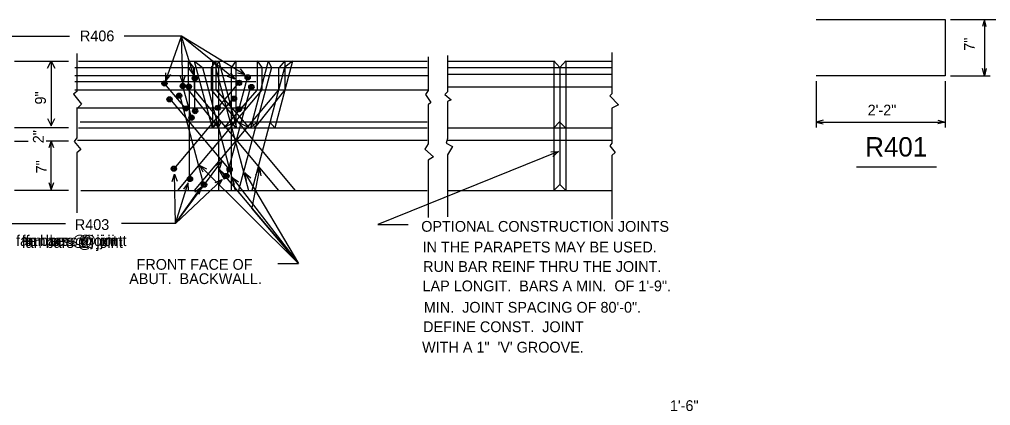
# Model space of a CAD drawing. Extents: x -3.6 to 32.6, y 15.5 to 40.2.
# Drawn here: x 9.24 to 20.52, y 24.58 to 29.06 of the extents above; entities that cross this region are included whole.
import ezdxf

# ---------------------------------------------------------------- set-up
doc = ezdxf.new("R2010")
doc.units = 0
for name, color, linetype in [('Level 2', 7, 'Continuous'), ('Level 3', 7, 'Continuous'), ('Level 4', 7, 'Continuous'), ('Level 5', 7, 'Continuous'), ('Level 6', 7, 'Continuous'), ('Level 7', 7, 'Continuous')]:
    doc.layers.add(name, color=color, linetype=linetype)

msp = doc.modelspace()

# ---------------------------------------------------------------- linework, layer by layer
at = {"layer": 'Level 2'}
for p, q in [((18.495, 29.063), (19.995, 29.063)), ((19.995, 29.063), (19.995, 28.411)), ((20.058, 29.063), (20.583, 29.063)), ((20.451, 29.055), (20.451, 28.432)), ((9.087, 28.87), (9.822, 28.87)), ((11.121, 28.87), (10.457, 28.87)), ((9.907, 28.668), (9.907, 28.229)), ((16.121, 28.678), (16.121, 28.199)), ((9.181, 28.58), (9.809, 28.58)), ((9.61, 28.58), (9.61, 27.834)), ((9.61, 28.58), (9.61, 27.83)), ((13.988, 28.631), (13.988, 28.238)), ((14.215, 28.647), (14.215, 28.223)), ((14.215, 28.58), (15.447, 28.58)), ((15.447, 28.584), (15.447, 27.08)), ((15.517, 28.505), (15.447, 28.584)), ((15.588, 28.584), (15.517, 28.505)), ((15.588, 28.584), (15.588, 27.08)), ((15.595, 28.58), (16.121, 28.58)), ((14.215, 28.505), (16.121, 28.505)), ((15.517, 28.505), (15.517, 27.15)), ((14.215, 28.43), (16.128, 28.43)), ((19.995, 28.411), (18.495, 28.411)), ((18.495, 28.348), (18.495, 27.811)), ((19.995, 28.348), (19.995, 27.811)), ((20.058, 28.411), (20.519, 28.411)), ((9.907, 28.229), (9.868, 28.198)), ((13.988, 28.238), (13.956, 28.192)), ((14.215, 28.223), (14.183, 28.192)), ((14.215, 28.28), (16.128, 28.28)), ((9.868, 28.198), (9.962, 28.08)), ((13.956, 28.192), (14.019, 28.098)), ((14.019, 28.098), (13.988, 28.074)), ((14.183, 28.192), (14.254, 28.129)), ((14.254, 28.129), (14.215, 28.113)), ((14.215, 28.113), (14.215, 27.682)), ((16.121, 28.199), (16.098, 28.176)), ((16.098, 28.176), (16.199, 28.074)), ((9.962, 28.08), (9.907, 28.025)), ((9.907, 28.025), (9.907, 27.688)), ((13.988, 28.074), (13.988, 27.619)), ((16.199, 28.074), (16.121, 28.035)), ((16.121, 28.035), (16.121, 27.627)), ((15.517, 27.878), (15.447, 27.807)), ((15.513, 27.876), (15.584, 27.805)), ((18.495, 27.873), (19.996, 27.873)), ((9.184, 27.81), (9.812, 27.81)), ((14.215, 27.805), (16.121, 27.805)), ((9.181, 27.651), (9.34, 27.651)), ((9.809, 27.651), (9.552, 27.651)), ((9.61, 27.088), (9.61, 27.656)), ((9.907, 27.688), (9.875, 27.648)), ((9.875, 27.648), (9.954, 27.554)), ((14.215, 27.682), (14.199, 27.627)), ((14.21, 27.663), (16.121, 27.663)), ((9.954, 27.554), (9.907, 27.515)), ((15.504, 27.531), (13.403, 26.685)), ((13.988, 27.619), (13.948, 27.557)), ((13.948, 27.557), (14.05, 27.47)), ((14.199, 27.627), (14.27, 27.588)), ((14.27, 27.588), (14.215, 27.493)), ((16.121, 27.627), (16.098, 27.596)), ((16.098, 27.596), (16.16, 27.518)), ((9.907, 27.515), (9.907, 26.819)), ((14.05, 27.47), (13.988, 27.431)), ((13.988, 27.431), (13.988, 26.764)), ((14.215, 27.493), (14.215, 26.772)), ((16.16, 27.518), (16.121, 27.486)), ((16.121, 27.486), (16.121, 26.748)), ((18.964, 27.354), (19.893, 27.354)), ((9.181, 27.084), (9.809, 27.084)), ((14.215, 27.08), (16.121, 27.08)), ((15.517, 27.15), (15.447, 27.079)), ((15.517, 27.15), (15.588, 27.079)), ((9.025, 26.696), (9.777, 26.696)), ((11.052, 26.696), (10.425, 26.696)), ((13.403, 26.685), (13.755, 26.685)), ((12.243, 26.233), (12.483, 26.233))]:
    msp.add_line(p, q, dxfattribs=at)
for points in [[(20.472, 28.98), (20.451, 29.063), (20.43, 28.98)], [(9.568, 28.497), (9.61, 28.58), (9.651, 28.497)], [(20.472, 28.495), (20.451, 28.411), (20.43, 28.495)], [(9.568, 27.913), (9.61, 27.83), (9.651, 27.913)], [(18.579, 27.894), (18.495, 27.873), (18.579, 27.852)], [(19.911, 27.894), (19.995, 27.873), (19.911, 27.852)], [(9.639, 27.572), (9.61, 27.656), (9.58, 27.572)], [(15.414, 27.527), (15.504, 27.531), (15.436, 27.472)], [(9.58, 27.173), (9.61, 27.088), (9.639, 27.173)]]:
    msp.add_lwpolyline(points, dxfattribs=at)
at = {"layer": 'Level 3'}
for p, q in [((11.262, 28.421), (11.121, 28.87)), ((9.925, 28.58), (11.482, 28.58)), ((11.482, 28.582), (11.482, 27.805)), ((11.482, 28.582), (11.544, 28.503)), ((11.756, 28.582), (11.701, 28.503)), ((11.748, 28.58), (13.976, 28.58)), ((11.756, 28.582), (11.756, 27.805)), ((9.884, 28.505), (11.55, 28.505)), ((11.552, 28.503), (11.552, 27.08)), ((11.7, 28.505), (13.976, 28.505)), ((11.701, 28.503), (11.701, 27.08)), ((9.884, 28.413), (11.552, 28.413)), ((11.413, 28.34), (9.884, 28.34)), ((11.279, 27.974), (11.279, 28.38)), ((11.693, 28.413), (13.988, 28.413)), ((9.884, 28.247), (11.552, 28.247)), ((11.216, 27.212), (11.216, 28.29)), ((11.693, 28.247), (13.988, 28.247)), ((11.433, 28.034), (9.904, 28.034)), ((9.945, 27.876), (11.55, 27.876)), ((11.552, 27.873), (11.482, 27.802)), ((11.7, 27.876), (13.976, 27.876)), ((11.701, 27.873), (11.756, 27.802)), ((9.925, 27.805), (11.55, 27.805)), ((11.7, 27.805), (13.976, 27.805)), ((9.915, 27.663), (11.55, 27.663)), ((11.7, 27.663), (13.976, 27.663)), ((11.552, 27.335), (12.483, 26.233)), ((11.554, 27.328), (11.618, 27.212)), ((11.655, 27.242), (11.554, 27.328)), ((11.701, 27.39), (11.701, 27.312)), ((11.618, 27.212), (11.655, 27.242)), ((9.955, 27.08), (11.55, 27.08)), ((11.052, 26.696), (11.2, 27.167)), ((11.7, 27.08), (13.976, 27.08))]:
    msp.add_line(p, q, dxfattribs=at)
for points in [[(11.209, 28.493), (11.262, 28.421), (11.265, 28.511)], [(11.203, 27.078), (11.2, 27.167), (11.147, 27.095)]]:
    msp.add_lwpolyline(points, dxfattribs=at)
for centre, radius in [((11.278, 28.381), 0.0304), ((11.278, 28.381), 0.0194), ((11.278, 28.381), 0.00907), ((11.208, 28.284), 0.0304), ((11.208, 28.284), 0.0194), ((11.208, 28.284), 0.00907), ((11.281, 28), 0.0304), ((11.281, 28), 0.0194), ((11.281, 28), 0.00907), ((11.221, 27.212), 0.0304), ((11.221, 27.212), 0.0194), ((11.221, 27.212), 0.00907)]:
    msp.add_circle(centre, radius, dxfattribs=at)
at = {"layer": 'Level 4'}
for p, q in [((11.138, 28.327), (11.121, 28.87)), ((9.925, 28.58), (11.271, 28.58)), ((11.271, 28.58), (11.479, 27.805)), ((11.273, 28.579), (11.365, 28.505)), ((11.555, 28.58), (11.516, 28.506)), ((11.555, 28.58), (13.976, 28.58)), ((11.555, 28.58), (11.763, 27.805)), ((9.884, 28.505), (11.365, 28.505)), ((11.365, 28.505), (11.747, 27.08)), ((11.519, 28.505), (13.976, 28.505)), ((11.519, 28.505), (11.9, 27.08)), ((9.884, 28.413), (11.387, 28.413)), ((11.315, 28.34), (9.884, 28.34)), ((11.544, 28.413), (13.988, 28.413)), ((9.884, 28.247), (11.428, 28.247)), ((11.245, 27.898), (11.139, 28.291)), ((11.593, 28.247), (13.988, 28.247)), ((11.381, 27.146), (11.102, 28.187)), ((11.433, 28.034), (9.904, 28.034)), ((9.945, 27.876), (11.534, 27.876)), ((11.535, 27.871), (11.479, 27.805)), ((11.687, 27.876), (13.976, 27.876)), ((11.691, 27.869), (11.763, 27.805)), ((9.925, 27.805), (11.479, 27.805)), ((11.763, 27.805), (13.976, 27.805)), ((9.915, 27.663), (11.591, 27.663)), ((11.744, 27.663), (13.976, 27.663)), ((11.803, 27.443), (11.823, 27.367)), ((11.711, 27.228), (12.483, 26.233)), ((9.955, 27.08), (11.747, 27.08)), ((11.052, 26.696), (11.351, 27.117)), ((11.9, 27.08), (13.976, 27.08))]:
    msp.add_line(p, q, dxfattribs=at)
for points in [[(11.164, 28.413), (11.138, 28.327), (11.106, 28.411)], [(11.74, 27.143), (11.711, 27.228), (11.786, 27.179)], [(11.278, 27.065), (11.351, 27.117), (11.325, 27.031)]]:
    msp.add_lwpolyline(points, dxfattribs=at)
for centre, radius in [((11.138, 28.291), 0.0304), ((11.095, 28.179), 0.0304), ((11.138, 28.291), 0.0194), ((11.138, 28.291), 0.00907), ((11.095, 28.179), 0.0194), ((11.095, 28.179), 0.00907), ((11.24, 27.923), 0.0304), ((11.24, 27.923), 0.0194), ((11.24, 27.923), 0.00907), ((11.385, 27.147), 0.0304), ((11.385, 27.147), 0.0194), ((11.385, 27.147), 0.00907)]:
    msp.add_circle(centre, radius, dxfattribs=at)
at = {"layer": 'Level 5'}
for p, q in [((11.86, 28.422), (11.121, 28.87)), ((9.925, 28.58), (12.13, 28.58)), ((12.13, 28.58), (11.923, 27.805)), ((12.13, 28.58), (12.169, 28.506)), ((12.414, 28.58), (12.207, 27.805)), ((12.413, 28.579), (12.321, 28.505)), ((12.414, 28.58), (13.976, 28.58)), ((9.884, 28.505), (12.167, 28.505)), ((12.167, 28.505), (11.785, 27.08)), ((12.321, 28.505), (11.939, 27.08)), ((12.321, 28.505), (13.976, 28.505)), ((9.884, 28.413), (12.143, 28.413)), ((11.988, 28.34), (9.884, 28.34)), ((11.786, 27.998), (11.891, 28.391)), ((12.296, 28.413), (13.988, 28.413)), ((9.884, 28.247), (12.098, 28.247)), ((11.649, 27.246), (11.928, 28.287)), ((12.252, 28.247), (13.988, 28.247)), ((11.882, 28.034), (9.904, 28.034)), ((9.945, 27.876), (11.999, 27.876)), ((11.995, 27.869), (11.923, 27.805)), ((12.151, 27.871), (12.207, 27.805)), ((12.152, 27.876), (13.976, 27.876)), ((9.925, 27.805), (11.923, 27.805)), ((12.207, 27.805), (13.976, 27.805)), ((9.915, 27.663), (11.942, 27.663)), ((12.095, 27.663), (13.976, 27.663)), ((11.883, 27.443), (11.862, 27.367)), ((11.052, 26.696), (11.595, 27.208)), ((11.86, 27.284), (12.483, 26.233)), ((9.955, 27.08), (11.785, 27.08)), ((11.939, 27.08), (13.976, 27.08))]:
    msp.add_line(p, q, dxfattribs=at)
for points in [[(11.803, 28.491), (11.86, 28.422), (11.773, 28.441)], [(11.513, 27.171), (11.595, 27.208), (11.553, 27.128)], [(11.878, 27.196), (11.86, 27.284), (11.928, 27.226)], [(11.878, 27.196), (11.86, 27.284), (11.928, 27.226)]]:
    msp.add_lwpolyline(points, dxfattribs=at)
for centre, radius in [((11.892, 28.391), 0.0304), ((11.892, 28.391), 0.0194), ((11.892, 28.391), 0.00907), ((11.935, 28.279), 0.0304), ((11.935, 28.279), 0.0194), ((11.935, 28.279), 0.00907), ((11.791, 28.023), 0.0304), ((11.791, 28.023), 0.0194), ((11.791, 28.023), 0.00907), ((11.645, 27.247), 0.0304), ((11.645, 27.247), 0.0194), ((11.645, 27.247), 0.00907)]:
    msp.add_circle(centre, radius, dxfattribs=at)
at = {"layer": 'Level 6'}
for p, q in [((10.942, 28.355), (11.121, 28.87)), ((9.925, 28.58), (11.201, 28.581)), ((11.201, 28.583), (11.201, 28.247)), ((11.201, 28.583), (11.264, 28.504)), ((11.521, 28.583), (11.466, 28.504)), ((11.513, 28.581), (13.976, 28.58)), ((11.521, 28.583), (11.521, 28.247)), ((9.884, 28.505), (11.269, 28.506)), ((11.272, 28.504), (11.272, 28.247)), ((11.465, 28.506), (13.976, 28.505)), ((11.466, 28.504), (11.466, 28.247)), ((9.884, 28.413), (11.272, 28.414)), ((11.132, 28.34), (9.884, 28.34)), ((11.188, 28.01), (10.927, 28.322)), ((11.458, 28.414), (13.988, 28.413)), ((9.884, 28.247), (11.272, 28.247)), ((11.201, 28.247), (11.548, 27.808)), ((11.272, 28.247), (12.251, 27.08)), ((11.466, 28.247), (13.988, 28.247)), ((11.466, 28.247), (12.445, 27.08)), ((11.521, 28.247), (11.908, 27.805)), ((11.68, 27.322), (10.987, 28.148)), ((11.302, 28.034), (9.904, 28.034)), ((9.945, 27.876), (11.583, 27.876)), ((11.583, 27.876), (11.55, 27.805)), ((11.777, 27.876), (11.908, 27.805)), ((11.777, 27.876), (13.976, 27.876)), ((9.925, 27.805), (11.55, 27.805)), ((11.908, 27.805), (13.976, 27.805)), ((9.915, 27.663), (11.761, 27.663)), ((11.955, 27.663), (13.976, 27.663)), ((11.983, 27.631), (12.033, 27.571)), ((11.052, 26.696), (11.591, 27.42)), ((12.03, 27.338), (11.94, 26.876)), ((9.955, 27.08), (12.251, 27.08)), ((12.445, 27.08), (13.976, 27.08)), ((12.483, 26.233), (11.941, 26.874))]:
    msp.add_line(p, q, dxfattribs=at)
for points in [[(10.997, 28.425), (10.942, 28.355), (10.942, 28.444)], [(11.517, 27.37), (11.591, 27.42), (11.564, 27.335)], [(11.985, 27.261), (12.03, 27.338), (12.043, 27.25)]]:
    msp.add_lwpolyline(points, dxfattribs=at)
for centre, radius in [((10.925, 28.321), 0.0304), ((10.925, 28.321), 0.0194), ((10.925, 28.321), 0.00907), ((10.984, 28.137), 0.0304), ((10.984, 28.137), 0.0194), ((10.984, 28.137), 0.00907), ((11.173, 28.031), 0.0304), ((11.173, 28.031), 0.0194), ((11.173, 28.031), 0.00907), ((11.683, 27.325), 0.0304), ((11.683, 27.325), 0.0194), ((11.683, 27.325), 0.00907)]:
    msp.add_circle(centre, radius, dxfattribs=at)
at = {"layer": 'Level 7'}
for p, q in [((11.741, 28.369), (11.121, 28.87)), ((9.925, 28.58), (12.002, 28.581)), ((12.002, 28.583), (12.002, 28.247)), ((12.002, 28.583), (12.057, 28.504)), ((12.322, 28.583), (12.259, 28.504)), ((12.322, 28.583), (12.322, 28.247)), ((12.322, 28.581), (13.976, 28.58)), ((9.884, 28.505), (12.057, 28.506)), ((12.057, 28.504), (12.057, 28.247)), ((12.251, 28.506), (13.976, 28.505)), ((12.251, 28.504), (12.251, 28.247)), ((12.251, 28.504), (12.251, 28.247)), ((12.251, 28.504), (12.251, 28.247)), ((9.884, 28.413), (12.057, 28.415)), ((9.884, 28.413), (11.272, 28.414)), ((11.93, 28.341), (9.884, 28.34)), ((11.529, 28.017), (11.79, 28.329)), ((12.251, 28.414), (13.988, 28.413)), ((9.884, 28.247), (12.057, 28.248)), ((12.057, 28.247), (11.078, 27.08)), ((12.251, 28.247), (11.272, 27.08)), ((12.251, 28.247), (11.272, 27.08)), ((12.251, 28.247), (11.272, 27.08)), ((12.002, 28.247), (11.615, 27.805)), ((12.322, 28.247), (11.975, 27.808)), ((12.251, 28.247), (13.988, 28.247)), ((11.037, 27.329), (11.73, 28.155)), ((11.688, 28.034), (9.904, 28.034)), ((9.945, 27.876), (11.746, 27.876)), ((11.746, 27.876), (11.615, 27.805)), ((11.94, 27.876), (11.973, 27.805)), ((11.94, 27.876), (13.976, 27.876)), ((9.925, 27.805), (11.687, 27.805)), ((11.88, 27.805), (13.976, 27.805)), ((9.915, 27.663), (11.568, 27.663)), ((11.761, 27.663), (13.976, 27.663)), ((11.54, 27.631), (11.49, 27.571)), ((11.54, 27.631), (11.49, 27.571)), ((11.54, 27.631), (11.49, 27.571)), ((11.334, 27.37), (12.483, 26.233)), ((11.052, 26.696), (11.042, 27.27)), ((9.955, 27.08), (11.078, 27.08)), ((11.272, 27.08), (13.976, 27.08)), ((12.445, 27.08), (13.976, 27.08)), ((12.445, 27.08), (13.976, 27.08))]:
    msp.add_line(p, q, dxfattribs=at)
for points in [[(11.694, 28.445), (11.741, 28.369), (11.657, 28.4)], [(11.374, 27.29), (11.334, 27.37), (11.415, 27.332)], [(11.014, 27.185), (11.042, 27.27), (11.073, 27.186)]]:
    msp.add_lwpolyline(points, dxfattribs=at)
for centre, radius in [((11.791, 28.328), 0.0304), ((11.791, 28.328), 0.0194), ((11.791, 28.328), 0.00907), ((11.733, 28.144), 0.0304), ((11.733, 28.144), 0.0194), ((11.733, 28.144), 0.00907), ((11.544, 28.038), 0.0304), ((11.544, 28.038), 0.0194), ((11.544, 28.038), 0.00907), ((11.034, 27.332), 0.0304), ((11.034, 27.332), 0.0194), ((11.034, 27.332), 0.00907)]:
    msp.add_circle(centre, radius, dxfattribs=at)

# ---------------------------------------------------------------- texts
at = {"layer": 'Level 2'}
for s, height, p in [('R406', 0.125, (9.943, 28.81)), ('R401', 0.225, (19.066, 27.473)), ('R403', 0.125, (9.884, 26.621)), ('OPTIONAL CONSTRUCTION JOINTS', 0.125, (13.908, 26.6)), ('IN THE PARAPETS MAY BE USED.', 0.125, (13.923, 26.36)), ('FRONT FACE OF', 0.125, (10.601, 26.159)), ('RUN BAR REINF THRU THE JOINT.', 0.125, (13.93, 26.134)), (' ABUT.  BACKWALL.', 0.125, (10.469, 25.993)), ('LAP LONGIT.  BARS A MIN.  OF 1\'-9".', 0.125, (13.923, 25.909)), ('MIN.  JOINT SPACING OF 80\'-0".', 0.125, (13.938, 25.661)), ('DEFINE CONST.  JOINT', 0.125, (13.93, 25.435)), ('WITH A 1"  \'V\' GROOVE.', 0.125, (13.918, 25.198)), ('1\'-6"', 0.125, (16.797, 24.52))]:
    msp.add_text(s, height=height, dxfattribs=at).set_placement(p)
for s, rotation, p in [('7"', 90, (20.339, 28.7)), (' 9" ', 90, (9.547, 28.03)), ('2\'-2"', 360, (19.094, 27.949)), ('2"', 90, (9.522, 27.627)), ('7"', 90, (9.558, 27.277))]:
    msp.add_text(s, height=0.125, rotation=rotation, dxfattribs=at).set_placement(p)
at = {"layer": 'Level 4'}
msp.add_text('fan bars @ joint', height=0.125, dxfattribs=at).set_placement((9.267, 26.435))
at = {"layer": 'Level 5'}
msp.add_text('fan bars @ joint', height=0.125, dxfattribs=at).set_placement((9.201, 26.435))
at = {"layer": 'Level 6'}
msp.add_text('fan bars @ joint', height=0.125, dxfattribs=at).set_placement((9.311, 26.434))
at = {"layer": 'Level 7'}
msp.add_text('fan bars @ joint', height=0.125, dxfattribs=at).set_placement((9.267, 26.413))

doc.saveas('drawing.dxf')
